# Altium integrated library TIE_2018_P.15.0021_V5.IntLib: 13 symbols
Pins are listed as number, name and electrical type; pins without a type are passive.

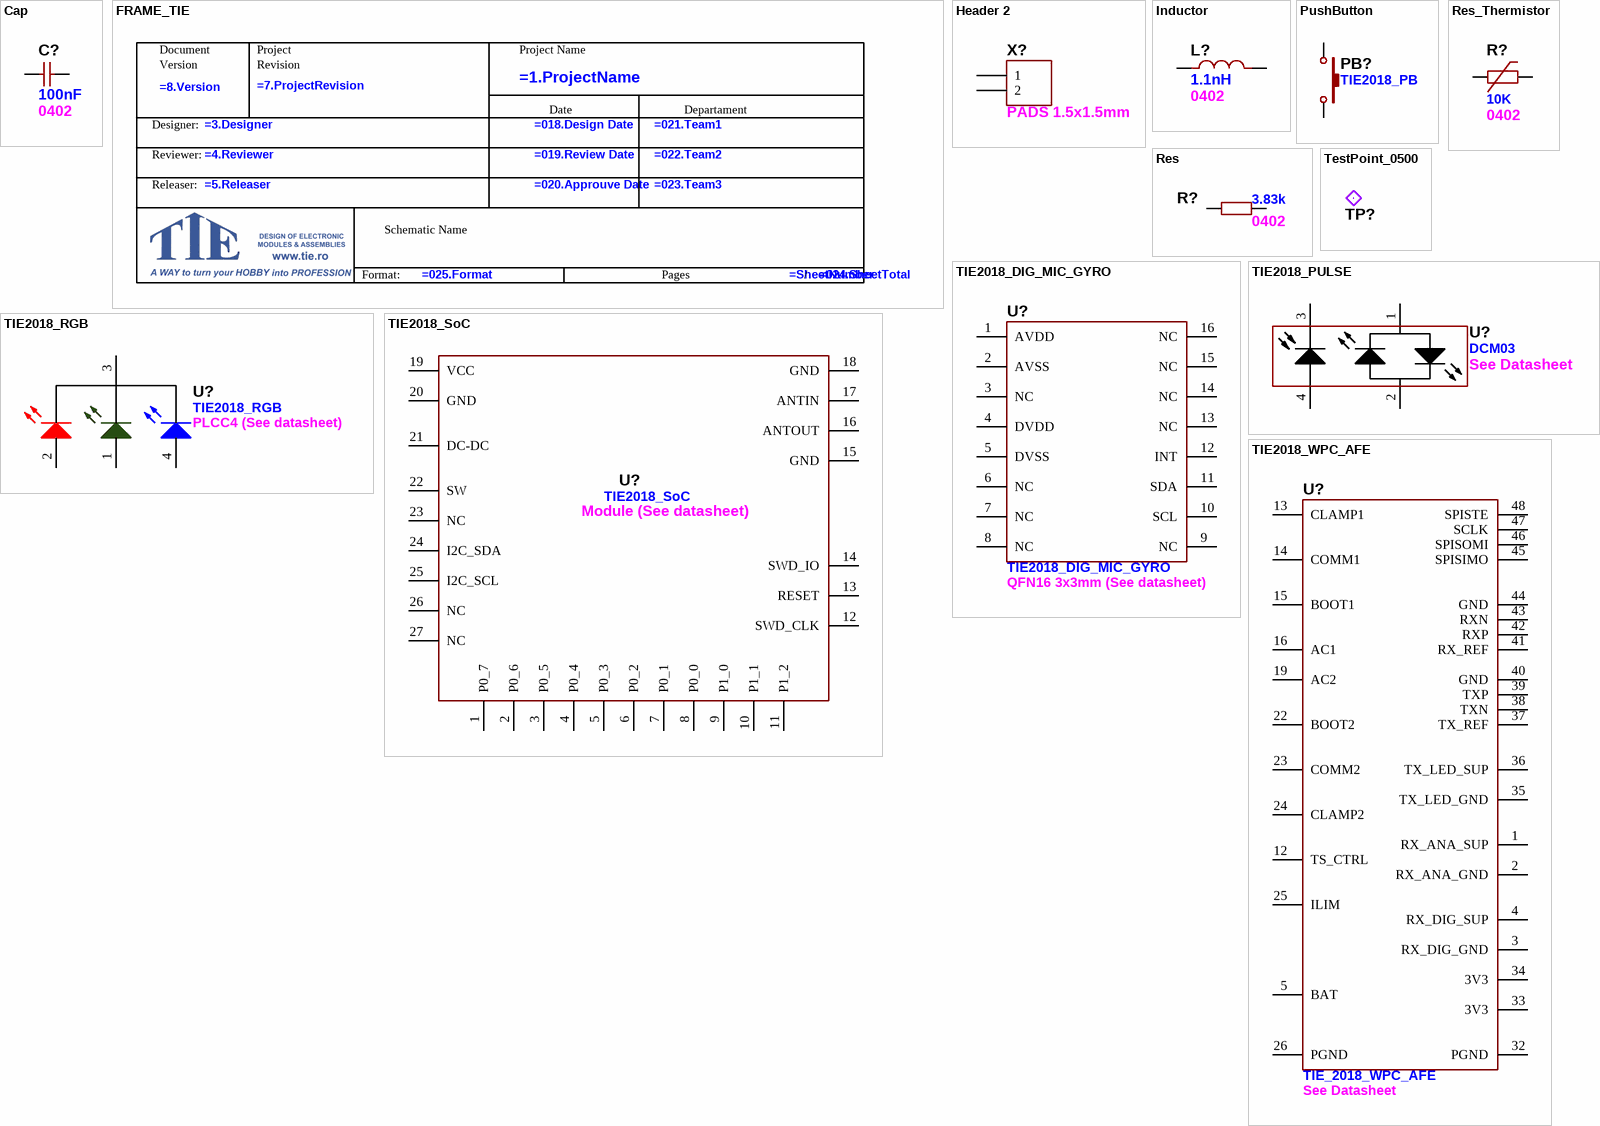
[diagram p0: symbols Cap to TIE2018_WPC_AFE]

## Cap
designator C?, comment 100nF  Footprint Name: 0402
footprint CAPC0603_0201H030 (Chip Capacitor, 2-Leads, Body 0.60x0.30mm, IPC Low Density)
footprint CAPC1005_0402H050 (Chip Capacitor, 2-Leads, Body 1.00x0.50mm, IPC Low Density)
footprint CAPC1608_0603H080 (Chip Capacitor, 2-Leads, Body 1.60x0.60mm, IPC Low Density)
footprint CAPC2012_0805H060 (Chip Capacitor, 2-Leads, Body 2.00x1.25mm, IPC Low Density)
footprint CAPC2012_0805H085 (Chip Capacitor, 2-Leads, Body 2.00x1.25mm, IPC Low Density)
footprint CAPC2012_0805H125 (Chip Capacitor, 2-Leads, Body 2.00x1.25mm, IPC Low Density)
footprint CAPC3216_1206H085 (Chip Capacitor, 2-Leads, Body 3.20x1.60mm, IPC Low Density)
footprint CAPC3216_1206H100 (Chip Capacitor, 2-Leads, Body 3.20x1.60mm, IPC Low Density)
footprint CAPC3216_1206H115 (Chip Capacitor, 2-Leads, Body 3.20x1.60mm, IPC Low Density)
pins: 1, 2

## FRAME_TIE
designator FRAME??  (graphical)
Frame Schematic

## Header 2
designator X?, comment PADS 1.5x1.5mm
footprint Contact Pads
pins: 1, 2

## Inductor
designator L?, comment 1.1nH  Footprint Name: 0402
footprint INDC0603_0201H030 (Chip Inductor, 2-Leads, Body 0.60x0.30mm, IPC Low Density)
footprint INDC1005_0402H050 (Chip Inductor, 2-Leads, Body 1.00x0.50mm, IPC Low Density)
footprint INDC1608_0603H080 (Chip Inductor, 2-Leads, Body 1.60x0.80mm, IPC Low Density)
footprint INDC1608_0603H102 (Chip Inductor, 2-Leads, Body 1.60x0.80mm, IPC Low Density)
footprint INDC2813_0805H152 (Chip Inductor, 2-Leads, Body 2.85x1.27mm, IPC High Density)
footprint INDC2813_0805H100 (Chip Inductor, 2-Leads, Body 2.85x1.27mm, IPC High Density)
pins: 1, 2

## PushButton
designator PB?, comment TIE2018_PB
footprint KXT 311 LHS (Ultra Low Profile Top Actuated 3.00x2.00x0.6mm)
footprint TIE_2018_PUSH_2.5x2.5
pins: 1, 2

## Res
designator R?, comment 3.83k  Footprint Name: 0402
footprint RESC0402_01005h013 (Chip Resistor, 2-Leads, Body 0.40x0.20mm, IPC Low Density)
footprint RESC0603_0201H023 (Chip Resistor, 2-Leads, Body 0.60x0.30mm, IPC Low Density)
footprint RESC1005_0402H035 (Chip Resistor, 2-Leads, Body 1.00x0.50mm, IPC Low Density)
footprint RESC1608_0603H045 (Chip Resistor, 2-Leads, Body 1.60x0.85mm, IPC Low Density)
footprint RESC2012_0805H060 (Chip Resistor, 2-Leads, Body 2.00x1.25mm, IPC Low Density)
footprint RESC3215_1206H060 (Chip Resistor, 2-Leads, Body 3.20x1.55mm, IPC Low Density)
pins: 1, 2

## Res_Thermistor
designator R?, comment 10K  Footprint Name: 0402
footprint RESC0402_01005h013 (Chip Resistor, 2-Leads, Body 0.40x0.20mm, IPC Low Density)
footprint RESC0603_0201H023 (Chip Resistor, 2-Leads, Body 0.60x0.30mm, IPC Low Density)
footprint RESC1005_0402H035 (Chip Resistor, 2-Leads, Body 1.00x0.50mm, IPC Low Density)
footprint RESC1608_0603H045 (Chip Resistor, 2-Leads, Body 1.60x0.85mm, IPC Low Density)
footprint RESC2012_0805H060 (Chip Resistor, 2-Leads, Body 2.00x1.25mm, IPC Low Density)
footprint RESC3215_1206H060 (Chip Resistor, 2-Leads, Body 3.20x1.55mm, IPC Low Density)
pins: 1, 2

## TestPoint_0500
designator TP?, comment 0.5mm  (value not drawn)
footprint TESTPOINT_500
pins: 1

## TIE2018_DIG_MIC_GYRO
designator U?  Footprint Name: QFN16 3x3mm (See datasheet)
footprint QFN16_P500_3000x3000x750_L (QFN, 16-Leads, Body 3.00x3.00mm, Pitch 0.50mm, Thermal Pad 2.50x2.50mm, IPC High Density)
pins: 1 AVDD, 2 AVSS, 3 NC, 4 DVDD, 5 DVSS, 6 NC, 7 NC, 8 NC, 9 NC, 10 SCL, 11 SDA, 12 INT, 13 NC, 14 NC, 15 NC, 16 NC

## TIE2018_PULSE
designator U?, comment DCM03  Footprint Name: See Datasheet
footprint DCM03
pins: 1, 2, 3, 4

## TIE2018_RGB
designator U?  Footprint Name: PLCC4 (See datasheet)
footprint PLCC4_LED
pins: 1 G, 2 R, 3 CK, 4 B

## TIE2018_SoC
designator U?  Footprint Name: Module (See datasheet)
footprint TIE2018-SoC
pins: 1 P0_7, 2 P0_6, 3 P0_5, 4 P0_4, 5 P0_3, 6 P0_2, 7 P0_1, 8 P0_0, 9 P1_0, 10 P1_1, 11 P1_2, 12 SWD_CLK, 13 RESET, 14 SWD_IO, 15 GND, 16 ANTOUT, 17 ANTIN, 18 GND, 19 VCC, 20 GND, 21 DC-DC, 22 SW, 23 NC, 24 I2C_SDA, 25 I2C_SCL, 26 NC, 27 NC

## TIE2018_WPC_AFE
designator U?, comment TIE_2018_WPC_AFE  Footprint Name: See Datasheet
footprint TIE2018_WPC-AFE
pins: 1 RX_ANA_SUP, 2 RX_ANA_GND, 3 RX_DIG_GND, 4 RX_DIG_SUP, 5 BAT, 12 TS_CTRL, 13 CLAMP1, 14 COMM1, 15 BOOT1, 16 AC1, 19 AC2, 22 BOOT2, 23 COMM2, 24 CLAMP2, 25 ILIM, 26 PGND, 32 PGND, 33 3V3, 34 3V3, 35 TX_LED_GND, 36 TX_LED_SUP, 37 TX_REF, 38 TXN, 39 TXP, 40 GND, 41 RX_REF, 42 RXP, 43 RXN, 44 GND, 45 SPISIMO, 46 SPISOMI, 47 SCLK, 48 SPISTE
